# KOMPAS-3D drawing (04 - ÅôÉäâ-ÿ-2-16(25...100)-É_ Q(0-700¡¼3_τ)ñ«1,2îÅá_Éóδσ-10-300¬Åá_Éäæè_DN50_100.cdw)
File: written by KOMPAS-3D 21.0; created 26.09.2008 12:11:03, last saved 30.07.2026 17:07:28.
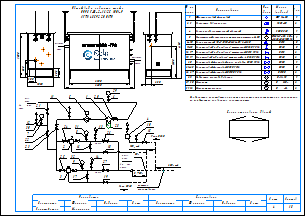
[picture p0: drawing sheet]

Sheets 1-2: A3, landscape

Document properties: Наименование: Макро:21; Автор: RaskoAdmin; Форматы листов документа: 2xA3; Полное имя файла: \\ur38nt01\Departments\КТО\КБ ПУРДГ\Заявки\Прайс-лист на типовые шкафы ГРПШ\ПУРДГ_стандарт_30_04_2026\ПУРДГ с РДСК\ПУРДГ-Ш-2-16(25...100)-Р_ Q(0-700нм3_ч)до1,2МПа_Рвых-10-300кПа_РДСК_DN50_100.cdw

Title block, sheet 1: Наименование: Пункт учета газа / ПУГ-Ш-400-Р / ЛГТИ.485922.001ТУ; designation: ЛГТИ.03.4411141; sheet number: 1; Количество листов документа: 2; organisation: ООО "ЭЛЬСТЕР Газэлектроника"; Форматы листов документа: A3; stored path: C:\Рабочие документы\Компас\ПУГ\Схема.cdw; Разработал: Устинов; Проверил: Кошкин; Утвердил: Кошкин
Title block, sheet 2: sheet number: 2; stored path: D:\Рабочие документы\Заявки\ПУРДГ\ПУРДГ-ШУЭО-2-100-Р 4411220.cdw; designation, second copy: ЛГТИ.03.4411141-

Views: Вид 1, Вид 2
Referenced files: wcvoit.frw
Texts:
  Normal
  № на
  схеме
  Усл.
  обозн.
  Марка
  (модель)
  Кол.
  Фильтр газовый фланцевый
  ФГ 16-50
  Регулятор давления газа
  РДСК-50
  Клапан предохранительный сбросной
  КПС DN20
  Измерительный комплекс с ротационным счетчиком Ду50
  СГ-ЭК-Р-(0,2...2,0)-
  Кран кнопочный VE-РАСКО-НЗ-1,6-G1/2-М20
  DN15
  Кран шаровой "под приварку" штуцерный DN20 PN16
  DN20
  Кран шаровой "под приварку" штуцерный DN15 PN16
  Кран шаровой "под приварку" штуцерный п/п DN20 PN16
  Кран шаровой фланцевый с мех. приводом DN50 PN16
  Кран шаровой фланцевый DN50 PN16
  Кран шаровой фланцевый DN100 PN16
  DN50
  DN100
  Индикатор перепада давления
  Манометр
  Манометр-напоромер
  Delta 15
  0...     МПа
  0...     кПа
  Общий вид и габариты шкафа
  ПУРДГ-Ш-2-16(25...100)-Р
  Выход газа
  Вход газа
  logo-rasko-ge.png
  DN 1
  местное
  сопротивление
  Римп DN20
  Выход
  газа
  Р=     кПа
  Вход
  Р=       МПа
  PDI
  Схема открывания дверей
  Предприятие изготовитель может заменять комплектующие на аналогичные,
  не ухудшающие заявленных характеристик.
  Должность
  Конструктор
  Фамилия
  Подпись
  Дата
  Согласовано
  Максимкин
  Лист
  Листов
  POLYLINE_STYLE_0.18_RGB_0_0_0
  POLYLINE_STYLE_0.50_RGB_0_0_0
  POLYLINE_STYLE_0.34_RGB_0_0_0
  PHANTOM_RGB_0_0_0_SC_1_THICK_0.18
  K5LT_THIN_RGB_0_0_0_THICK_0.18
  K5LT32769_RGB_0_0_0_THICK_0.18
  K5LT12_RGB_0_0_0_SC_1_THICK_0.18
  K5LT_DASHED_RGB_0_0_0_SC_1_THICK_0.18
  ACISOTGL_RGB_0_0_0_SC_0.8_THICK_0.25
  CONTINUOUS_RGB_0_127_31_THICK_0.3
  CONTINUOUS_RGB_0_0_255_THICK_0.35
  CONTINUOUS_RGB_255_0_0_THICK_0.35
  POLYLINE_STYLE_0.25_RGB_0_0_0
  CONTINUOUS_RGB_0_0_0_THICK_0.5
  POLYLINE_STYLE_0.35_RGB_0_0_255
  CONTINUOUS_RGB_0_0_0_THICK_0.4
  CONTINUOUS_RGB_0_0_0_THICK_0.35
  НЕВИДИМАЯ_RGB_0_0_0_SC_0.3_THICK_0.25
  СONTINUOUS_RGB_0_0_0_THICK_0.25
  ОСЕВАЯ2_RGB_248_153_30_SC_0.3_THICK_0.25
  Без оформления
Dimensions and other numbers on the sheet: 1; 2, 3; 2; 4; 5; 6-10; 11-15; 16, 17; 18, 19; 20; 21-25; 26, 27; 28; 29, 30; 31, 32; 1500; 250; 300; 1050; 550; 305; 2300; 4130; 2000; 2600; 5,,,7DN 1; 7; 30; 12; 21; 22; 23; 11; 6; 29; 24; 31; 8; 16; 13; 26; 18; 10; 15; 25; 32; 9; 3; 17; 14; 27; 19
